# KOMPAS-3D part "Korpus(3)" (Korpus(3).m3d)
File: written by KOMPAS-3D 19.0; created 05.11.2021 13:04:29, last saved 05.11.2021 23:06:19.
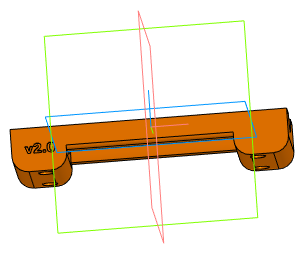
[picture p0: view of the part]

Document properties: Полное имя файла: D:\3D_print\3D проекты Компас 3D\Редуктор (Снова)\Korpus(3).m3d

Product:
- Part/product: Korpus(3)
    Материал: АБС 0603Т ТУ 2214-019-002 03521-96 (density 0 kg/m3)

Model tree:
1. Эскиз:1  (with: Элемент выдавливания:1)  (labels: Korpus(3); Korpus(1))
2. Элемент выдавливания:1  (labels: Korpus(1); Korpus(3))
     Расстояние 1 = 34.6; Расстояние 2 = 34.6
3. Эскиз:2  (labels: Korpus(3))
4. Элемент выдавливания:2  (with: Элемент выдавливания:11)  (labels: Korpus(1); Korpus(3))
     Расстояние 1 = 20.9; Расстояние 2 = 20.9
5. Эскиз:3  (labels: Korpus(3))
6. Элемент выдавливания:3  (labels: Подшипник 23 ГОСТ 8338-75\Наружное кольцо; Korpus(3); Операция вращения:1; Операция вращения:1)
     Расстояние 1 = -25.2; Смещение 1 = 0.3; Расстояние 2 = -25.2; Смещение 2 = 0.3
7. Эскиз:4  (with: Элемент выдавливания:1)
8. Элемент выдавливания:4  (with: Элемент выдавливания:1)
     Расстояние 2 = 23
9. Скругление:1  (with: Элемент выдавливания:4, Элемент выдавливания:1)
     Радиус = 4
10. Скругление:2  (with: Элемент выдавливания:4)
     Радиус = 1
11. Эскиз:5  (with: Элемент выдавливания:1, Элемент выдавливания:12)  (labels: Korpus(2); Korpus(3))
12. Элемент выдавливания:5
     Расстояние 2 = 11.0259
13. Эскиз:6  (with: Элемент выдавливания:1)
14. Элемент выдавливания:6  (labels: АБС 0603Т ТУ 2214-019-002 03521-96)

Referenced files in D:\3D_print\3D проекты Компас 3D\Редуктор (Снова)\: R-10 - Reductor.a3d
